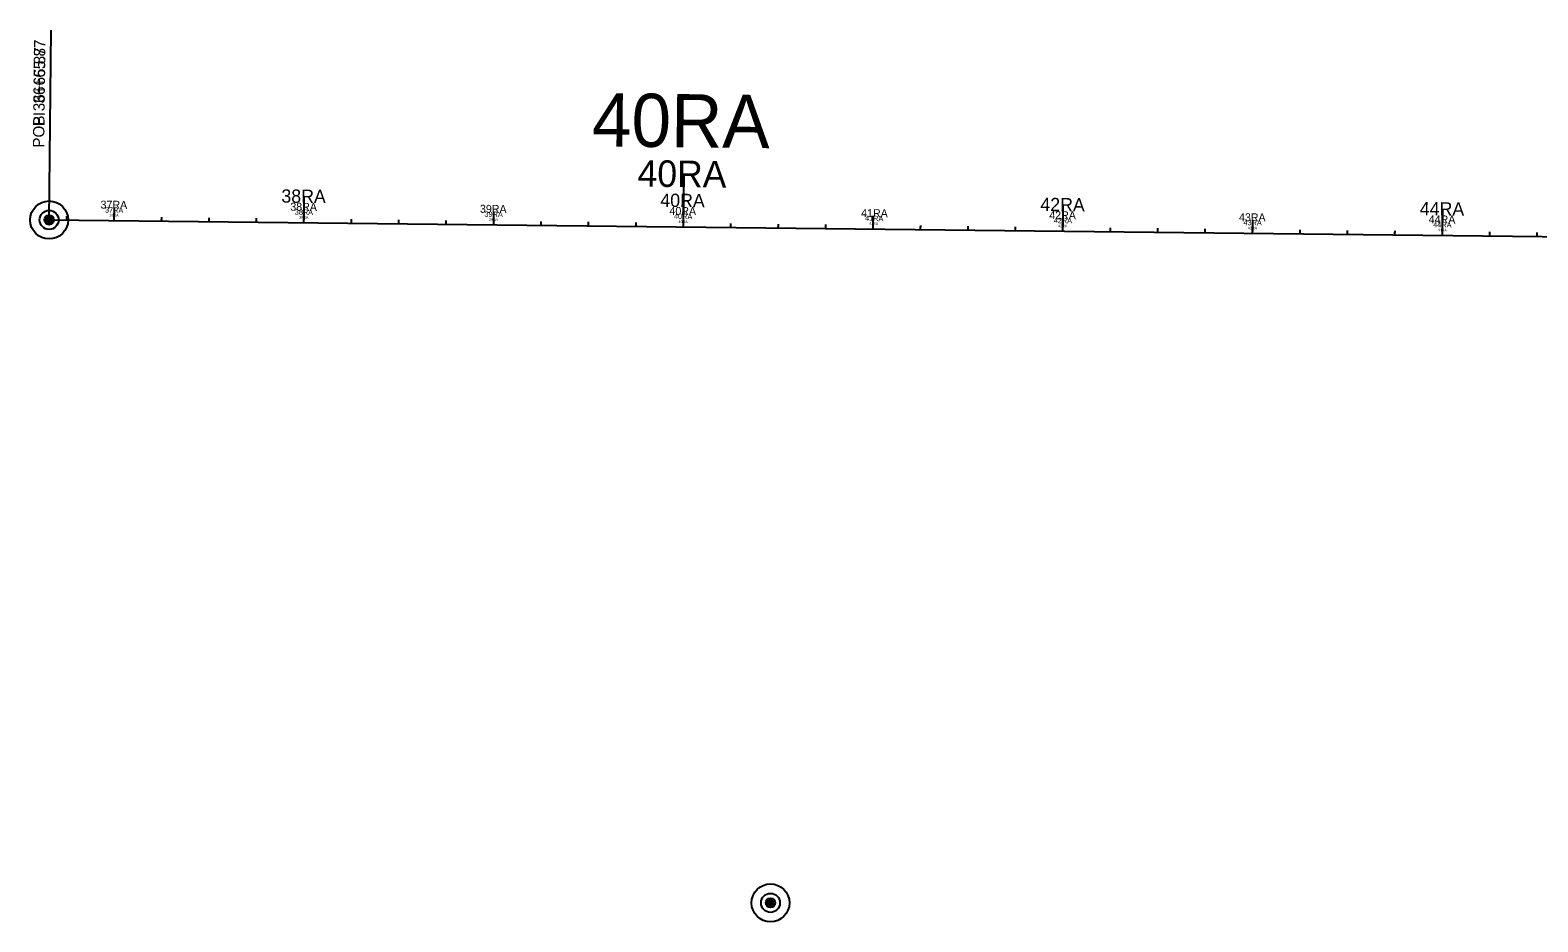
# Model space of a CAD drawing. Extents: x 564646 to 607088, y 225853 to 261760.
# Drawn here: x 597606 to 598400, y 254636 to 255106 of the extents above; entities that cross this region are included whole.
import ezdxf

# ---------------------------------------------------------------- set-up
doc = ezdxf.new("R2010")
doc.units = 0
for name, color, linetype in [('B_CONC_HIDDEN_LT', 7, 'Continuous'), ('B_CONST', 7, 'Continuous'), ('B_EXIST', 7, 'Continuous'), ('B_TEXT', 7, 'Continuous'), ('E-Easements', 7, 'Continuous'), ('E-Property Lines', 7, 'Continuous'), ('E_ALI_100', 7, 'Continuous'), ('E_RW_CorporateLimits', 7, 'Continuous'), ('E_RW_EasementUtility_Text', 7, 'Continuous'), ('E_WTR_FlowLine', 7, 'Continuous'), ('EMCS_SURVEY_PT CODES', 7, 'Continuous'), ('EMCS_SURVEY_PT ELEV', 7, 'Continuous'), ('EMCS_SURVEY_PT NOTES', 7, 'Continuous'), ('Level 33', 7, 'Continuous'), ('P-Easements Floodplain', 7, 'Continuous'), ('P-Easements Temporary', 7, 'Continuous'), ('P_ALI_100_Tic', 7, 'Continuous'), ('P_ALI_20', 7, 'Continuous'), ('P_ALI_50', 7, 'Continuous'), ('P_RW_AccessPreviousProject Txt', 7, 'Continuous'), ('P_RW_EasementPerm', 7, 'Continuous'), ('P_RW_EasementTemp', 7, 'Continuous'), ('P_RW_PropertyConnector', 7, 'Continuous'), ('P_RW_Proposed', 7, 'Continuous'), ('P_WAL', 7, 'Continuous')]:
    doc.layers.add(name, color=color, linetype=linetype)

msp = doc.modelspace()

# ---------------------------------------------------------------- linework, layer by layer
at = {"layer": 'B_CONC_HIDDEN_LT'}
msp.add_line((597615.91, 255005.79), (600274.63, 254976.34), dxfattribs=at)
at = {"layer": 'B_CONST'}
for centre in [(597615.91, 255005.79), (597996.08, 254646)]:
    msp.add_circle(centre, 1.5, dxfattribs=at)
at = {"layer": 'B_EXIST'}
for centre in [(597615.91, 255005.79), (597996.08, 254646)]:
    msp.add_circle(centre, 5, dxfattribs=at)
at = {"layer": 'B_TEXT'}
msp.add_lwpolyline([(597615.91, 255005.79), (597617.02, 255105.78)], dxfattribs=at)
at = {"layer": 'E-Easements'}
for centre in [(597615.91, 255005.79), (597996.08, 254646)]:
    msp.add_circle(centre, 2.5, dxfattribs=at)
at = {"layer": 'E_ALI_100'}
for points in [[(597625.05, 255007.09), (597625.04, 255005.69)], [(597650.07, 255008.21), (597650.04, 255005.41)], [(597675.05, 255006.53), (597675.04, 255005.14)], [(597750.06, 255007.1), (597750.03, 255004.3)], [(597700.05, 255006.26), (597700.03, 255004.86)], [(597725.05, 255005.98), (597725.03, 255004.58)], [(597775.05, 255005.43), (597775.03, 255004.03)], [(597800.04, 255005.15), (597800.03, 255003.75)], [(597825.04, 255004.87), (597825.03, 255003.47)], [(597850.06, 255006), (597850.03, 255003.2)], [(597875.04, 255004.32), (597875.02, 255002.92)], [(597900.04, 255004.04), (597900.02, 255002.64)], [(597925.04, 255003.77), (597925.02, 255002.37)], [(597950.05, 255004.89), (597950.02, 255002.09)], [(597975.03, 255003.21), (597975.02, 255001.81)], [(598000.03, 255002.94), (598000.02, 255001.54)], [(598025.03, 255002.66), (598025.01, 255001.26)], [(598050.04, 255003.78), (598050.01, 255000.98)], [(598075.03, 255002.1), (598075.01, 255000.7)], [(598100.03, 255001.83), (598100.01, 255000.43)], [(598125.02, 255001.55), (598125.01, 255000.15)], [(598150.04, 255002.67), (598150.01, 254999.87)], [(598175.02, 255001), (598175.01, 254999.6)], [(598200.02, 255000.72), (598200, 254999.32)], [(598225.02, 255000.44), (598225, 254999.04)], [(598250.03, 255001.57), (598250, 254998.77)], [(598275.02, 254999.89), (598275, 254998.49)], [(598300.01, 254999.61), (598300, 254998.21)], [(598325.01, 254999.34), (598325, 254997.94)], [(598350.03, 255000.46), (598349.99, 254997.66)], [(598375.01, 254998.78), (598374.99, 254997.38)], [(598400.01, 254998.5), (598399.99, 254997.1)]]:
    msp.add_lwpolyline(points, dxfattribs=at)
at = {"layer": 'E_WTR_FlowLine'}
for centre in [(597615.91, 255005.79), (597996.08, 254646)]:
    msp.add_circle(centre, 0.5, dxfattribs=at)
at = {"layer": 'EMCS_SURVEY_PT CODES'}
msp.add_line((597615.91, 255005.79), (600274.63, 254976.34), dxfattribs=at)
at = {"layer": 'EMCS_SURVEY_PT ELEV'}
msp.add_line((597615.91, 255005.79), (600274.63, 254976.34), dxfattribs=at)
at = {"layer": 'Level 33'}
for points in [[(597625.05, 255006.39), (597625.04, 255005.69)], [(597650.05, 255006.81), (597650.04, 255005.41)], [(597675.04, 255005.84), (597675.04, 255005.14)], [(597700.04, 255005.56), (597700.03, 255004.86)], [(597725.04, 255005.28), (597725.03, 255004.58)], [(597750.05, 255005.7), (597750.03, 255004.3)], [(597775.04, 255004.73), (597775.03, 255004.03)], [(597800.04, 255004.45), (597800.03, 255003.75)], [(597825.03, 255004.17), (597825.03, 255003.47)], [(597850.04, 255004.6), (597850.03, 255003.2)], [(597875.03, 255003.62), (597875.02, 255002.92)], [(597900.03, 255003.34), (597900.02, 255002.64)], [(597925.03, 255003.07), (597925.02, 255002.37)], [(597950.04, 255003.49), (597950.02, 255002.09)], [(597975.03, 255002.51), (597975.02, 255001.81)], [(598000.02, 255002.24), (598000.02, 255001.54)], [(598025.02, 255001.96), (598025.01, 255001.26)], [(598050.03, 255002.38), (598050.01, 255000.98)], [(598075.02, 255001.4), (598075.01, 255000.7)], [(598100.02, 255001.13), (598100.01, 255000.43)], [(598125.02, 255000.85), (598125.01, 255000.15)], [(598150.02, 255001.27), (598150.01, 254999.87)], [(598175.01, 255000.3), (598175.01, 254999.6)], [(598200.01, 255000.02), (598200, 254999.32)], [(598225.01, 254999.74), (598225, 254999.04)], [(598250.02, 255000.17), (598250, 254998.77)], [(598275.01, 254999.19), (598275, 254998.49)], [(598300.01, 254998.91), (598300, 254998.21)], [(598325, 254998.64), (598325, 254997.94)], [(598350.01, 254999.06), (598349.99, 254997.66)], [(598375, 254998.08), (598374.99, 254997.38)], [(598400, 254997.8), (598399.99, 254997.1)]]:
    msp.add_lwpolyline(points, dxfattribs=at)
at = {"layer": 'P-Easements Floodplain'}
msp.add_line((597615.91, 255005.79), (600274.63, 254976.34), dxfattribs=at)
at = {"layer": 'P-Easements Temporary'}
for centre in [(597615.91, 255005.79), (597996.08, 254646)]:
    msp.add_circle(centre, 10, dxfattribs=at)
at = {"layer": 'P_ALI_100_Tic'}
for points in [[(597950.33, 255030.09), (597950.02, 255002.09)], [(597750.19, 255018.3), (597750.03, 255004.3)], [(598150.16, 255013.87), (598150.01, 254999.87)], [(598350.15, 255011.66), (598349.99, 254997.66)]]:
    msp.add_lwpolyline(points, dxfattribs=at)
at = {"layer": 'P_ALI_20'}
for points in [[(597950.17, 255016.09), (597950.02, 255002.09)], [(597650.12, 255012.41), (597650.04, 255005.41)], [(597750.11, 255011.3), (597750.03, 255004.3)], [(597850.1, 255010.2), (597850.03, 255003.2)], [(598050.09, 255007.98), (598050.01, 255000.98)], [(598150.08, 255006.87), (598150.01, 254999.87)], [(598250.08, 255005.77), (598250, 254998.77)], [(598350.07, 255004.66), (598349.99, 254997.66)]]:
    msp.add_lwpolyline(points, dxfattribs=at)
at = {"layer": 'P_ALI_50'}
msp.add_lwpolyline([(597615.91, 255005.79), (597617.02, 255105.78)], dxfattribs=at)
at = {"layer": 'P_RW_AccessPreviousProject Txt'}
for points in [[(597625.06, 255007.79), (597625.04, 255005.69)], [(597650.08, 255009.61), (597650.04, 255005.41)], [(597675.06, 255007.23), (597675.04, 255005.14)], [(597700.06, 255006.96), (597700.03, 255004.86)], [(597725.06, 255006.68), (597725.03, 255004.58)], [(597750.08, 255008.5), (597750.03, 255004.3)], [(597850.07, 255007.4), (597850.03, 255003.2)], [(597775.05, 255006.13), (597775.03, 255004.03)], [(597800.05, 255005.85), (597800.03, 255003.75)], [(597825.05, 255005.57), (597825.03, 255003.47)], [(597875.05, 255005.02), (597875.02, 255002.92)], [(597900.05, 255004.74), (597900.02, 255002.64)], [(597925.04, 255004.47), (597925.02, 255002.37)], [(597950.07, 255006.29), (597950.02, 255002.09)], [(597975.04, 255003.91), (597975.02, 255001.81)], [(598000.04, 255003.64), (598000.02, 255001.54)], [(598025.04, 255003.36), (598025.01, 255001.26)], [(598050.06, 255005.18), (598050.01, 255000.98)], [(598075.04, 255002.8), (598075.01, 255000.7)], [(598100.03, 255002.53), (598100.01, 255000.43)], [(598125.03, 255002.25), (598125.01, 255000.15)], [(598150.05, 255004.07), (598150.01, 254999.87)], [(598175.03, 255001.7), (598175.01, 254999.6)], [(598200.03, 255001.42), (598200, 254999.32)], [(598225.03, 255001.14), (598225, 254999.04)], [(598250.05, 255002.97), (598250, 254998.77)], [(598275.02, 255000.59), (598275, 254998.49)], [(598300.02, 255000.31), (598300, 254998.21)], [(598325.02, 255000.04), (598325, 254997.94)], [(598350.04, 255001.86), (598349.99, 254997.66)], [(598375.02, 254999.48), (598374.99, 254997.38)], [(598400.02, 254999.2), (598399.99, 254997.1)]]:
    msp.add_lwpolyline(points, dxfattribs=at)
at = {"layer": 'P_RW_EasementPerm'}
for points in [[(597650.08, 255008.91), (597650.04, 255005.41)], [(597750.11, 255011.3), (597750.03, 255004.3)], [(597850.06, 255006.7), (597850.03, 255003.2)], [(597950.1, 255009.09), (597950.02, 255002.09)], [(598150.08, 255006.87), (598150.01, 254999.87)], [(598050.05, 255004.48), (598050.01, 255000.98)], [(598250.04, 255002.27), (598250, 254998.77)], [(598350.07, 255004.66), (598349.99, 254997.66)]]:
    msp.add_lwpolyline(points, dxfattribs=at)
at = {"layer": 'P_RW_EasementTemp'}
msp.add_line((597615.91, 255005.79), (600274.63, 254976.34), dxfattribs=at)
at = {"layer": 'P_RW_PropertyConnector'}
msp.add_line((597615.91, 255005.79), (600274.63, 254976.34), dxfattribs=at)
at = {"layer": 'P_WAL'}
for centre in [(597615.91, 255005.79), (597996.08, 254646)]:
    msp.add_circle(centre, 1, dxfattribs=at)

# ---------------------------------------------------------------- texts
for s, p in [('37RA', (597645.33, 255009.66)), ('38RA', (597745.33, 255008.56)), ('39RA', (597845.3, 255007.45)), ('40RA', (597945.21, 255006.34)), ('41RA', (598045.88, 255005.23)), ('42RA', (598145.3, 255004.13)), ('43RA', (598245.3, 255003.02)), ('44RA', (598345.29, 255001.91))]:
    msp.add_text(s, height=2.8, rotation=359.36537).set_placement(p)
at = {"layer": 'B_TEXT'}
msp.add_text('POB 36+65.87', height=6, rotation=89.36537, dxfattribs=at).set_placement((597613.33, 255043.84))
at = {"layer": 'E-Property Lines'}
msp.add_text('40RA', height=28, rotation=359.36537, dxfattribs=at).set_placement((597901.88, 255044.63))
at = {"layer": 'E_RW_CorporateLimits'}
msp.add_text('40RA', height=14, rotation=359.36537, dxfattribs=at).set_placement((597925.95, 255023.36))
at = {"layer": 'E_RW_EasementUtility_Text'}
for s, p in [('37RA', (597647.69, 255007.54)), ('38RA', (597747.68, 255006.43)), ('39RA', (597847.66, 255005.32)), ('40RA', (597947.61, 255004.22)), ('41RA', (598047.95, 255003.1)), ('42RA', (598147.66, 255002)), ('43RA', (598247.65, 255000.89)), ('44RA', (598347.64, 254999.78))]:
    msp.add_text(s, height=1.4, rotation=359.36537, dxfattribs=at).set_placement(p)
at = {"layer": 'EMCS_SURVEY_PT NOTES'}
for s, p in [('37RA', (597642.98, 255011.79)), ('38RA', (597742.98, 255010.68)), ('39RA', (597842.94, 255009.58)), ('40RA', (597942.8, 255008.47)), ('41RA', (598043.82, 255007.35)), ('42RA', (598142.95, 255006.25)), ('43RA', (598242.94, 255005.14)), ('44RA', (598342.94, 255004.04))]:
    msp.add_text(s, height=4.2, rotation=359.36537, dxfattribs=at).set_placement(p)
at = {"layer": 'P_ALI_50'}
msp.add_text('PI  36+65.87', height=6, rotation=89.36537, dxfattribs=at).set_placement((597613.46, 255055.08))
at = {"layer": 'P_RW_Proposed'}
for s, p in [('38RA', (597738.27, 255014.94)), ('40RA', (597937.98, 255012.72)), ('42RA', (598138.25, 255010.5)), ('44RA', (598338.23, 255008.29))]:
    msp.add_text(s, height=7, rotation=359.36537, dxfattribs=at).set_placement(p)

doc.saveas('drawing.dxf')
